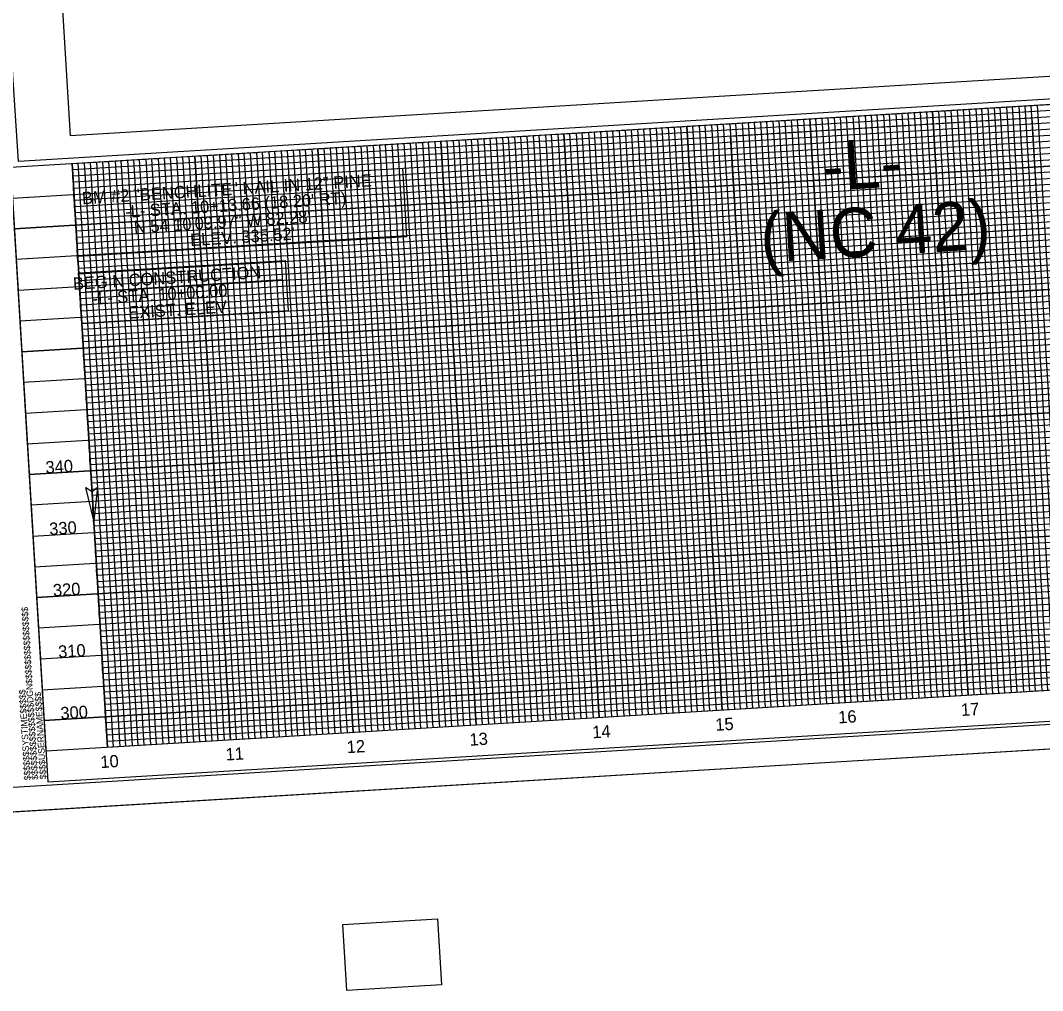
# Model space of a CAD drawing. Extents: x 2110128 to 2112690, y 669500 to 671339.
# Drawn here: x 2110982 to 2111812, y 669502 to 670290 of the extents above; entities that cross this region are included whole.
import ezdxf

# ---------------------------------------------------------------- set-up
doc = ezdxf.new("R2010")
doc.units = 0
for name, color, linetype in [('COGO Default Chain', 7, 'Continuous'), ('Exist Building', 7, 'Continuous'), ('Exist Building Leader', 7, 'Continuous'), ('Exist Guardrail', 7, 'Continuous'), ('Exist Other Culture Area Outline', 7, 'Continuous'), ('Exist Other Culture Fence Line', 7, 'Continuous'), ('Exist Other Culture Sign Leader', 7, 'Continuous'), ('Exist Roads Curbs', 7, 'Continuous'), ('Exist Roads Curbs Text', 7, 'Continuous'), ('Exist Roads EOP Other Text', 7, 'Continuous'), ('Exist Roads Soil', 7, 'Continuous'), ('Exist Structure Minor Footbridge', 7, 'Continuous'), ('Exist Structure Minor Pipes CMP 60 Inch', 7, 'Continuous'), ('Exist Utilities TV Hand Hole CELL', 7, 'Continuous'), ('Exist Utilities TV Test Hole SUE LOS A Text', 7, 'Continuous'), ('Exist Utilities Water Fire Hydrant CELL', 7, 'Continuous'), ('Exist Utilities Water Fire Hydrant Cogo Number', 7, 'Continuous'), ('Exist Utilities Water Test Hole SUE LOS A Text', 7, 'Continuous')]:
    doc.layers.add(name, color=color, linetype=linetype)

msp = doc.modelspace()

# ---------------------------------------------------------------- linework, layer by layer
at = {"layer": 'COGO Default Chain'}
for points in [[(2111558.56, 670196.14), (2111803.11, 670210.96), (2111810.07, 670096.17), (2111565.52, 670081.35)], [(2111025.15, 670153.72), (2111292.17, 670169.9), (2111295.54, 670114.39), (2111028.52, 670098.2)], [(2111029.32, 670085.02), (2111196.98, 670095.18), (2111199.47, 670054.16), (2111031.8, 670044)], [(2111243.72, 669555.89), (2111320.65, 669560.56), (2111323.9, 669506.88), (2111246.97, 669502.22)]]:
    msp.add_lwpolyline(points, close=True, dxfattribs=at)
at = {"layer": 'Exist Building'}
for points in [[(2110974.03, 670170.73), (2112471.28, 670261.48)], [(2111751.39, 669741.97), (2111722.66, 670216.1), (2111772.56, 670219.13), (2111801.3, 669745)], [(2112474.31, 670211.57), (2110977.05, 670120.82), (2110980.08, 670070.92), (2112477.33, 670161.66)], [(2111651.57, 669735.92), (2111622.84, 670210.05), (2111672.75, 670213.08), (2111701.48, 669738.95)], [(2111451.94, 669723.83), (2111423.21, 670197.96), (2111473.11, 670200.98), (2111501.85, 669726.85)], [(2111551.76, 669729.88), (2111523.02, 670204.01), (2111572.93, 670207.03), (2111601.67, 669732.9)], [(2111352.12, 669717.78), (2111323.39, 670191.91), (2111373.3, 670194.93), (2111402.03, 669720.8)], [(2111152.49, 669705.68), (2111123.76, 670179.81), (2111173.66, 670182.83), (2111202.4, 669708.7)], [(2111252.31, 669711.73), (2111223.57, 670185.86), (2111273.48, 670188.88), (2111302.22, 669714.75)], [(2111052.67, 669699.63), (2111023.94, 670173.76), (2111073.85, 670176.78), (2111102.58, 669702.65)], [(2110974.03, 670170.73), (2111002.77, 669696.6)], [(2112480.36, 670111.75), (2110983.1, 670021.01), (2110986.13, 669971.1), (2112483.38, 670061.84)], [(2112486.41, 670011.93), (2110989.15, 669921.19), (2110992.18, 669871.28), (2112489.43, 669962.03)], [(2112492.46, 669912.12), (2110995.2, 669821.37), (2110998.23, 669771.47), (2112495.48, 669862.21)], [(2112498.51, 669812.3), (2111001.25, 669721.56)]]:
    msp.add_lwpolyline(points, dxfattribs=at)
at = {"layer": 'Exist Building Leader'}
for points in [[(2112421.68, 670253.46), (2111024.24, 670168.77)], [(2112422.28, 670243.48), (2111024.85, 670158.79), (2111024.54, 670163.78), (2112421.98, 670248.47)], [(2112423.19, 670228.51), (2111025.75, 670143.81), (2111025.45, 670148.8), (2111025.15, 670153.79), (2112422.58, 670238.49)], [(2112423.79, 670218.52), (2111026.36, 670133.83), (2111026.06, 670138.82), (2112423.49, 670223.52)], [(2111741.41, 669741.37), (2111712.67, 670215.5), (2111717.67, 670215.8), (2111746.4, 669741.67)], [(2111756.38, 669742.28), (2111727.65, 670216.41), (2111732.64, 670216.71), (2111761.37, 669742.58)], [(2111766.36, 669742.88), (2111737.63, 670217.01), (2111742.62, 670217.31), (2111771.36, 669743.18)], [(2111781.34, 669743.79), (2111752.6, 670217.92), (2111757.59, 670218.22), (2111786.33, 669744.09)], [(2111791.32, 669744.39), (2111762.58, 670218.52), (2111767.57, 670218.83), (2111796.31, 669744.7)], [(2111806.29, 669745.3), (2111777.56, 670219.43), (2111782.55, 670219.73), (2111811.28, 669745.6)], [(2111816.27, 669745.91), (2111787.54, 670220.04), (2111792.53, 670220.34), (2111821.26, 669746.21)], [(2111831.25, 669746.81), (2111802.51, 670220.94), (2111807.5, 670221.25), (2111836.24, 669747.12)], [(2112424.7, 670203.55), (2111027.27, 670118.86), (2111026.96, 670123.85), (2111026.66, 670128.84), (2112424.1, 670213.53)], [(2111606.66, 669733.2), (2111577.92, 670207.33), (2111582.91, 670207.64), (2111611.65, 669733.51)], [(2111616.64, 669733.81), (2111587.9, 670207.94), (2111592.89, 670208.24), (2111621.63, 669734.11)], [(2111631.61, 669734.71), (2111602.88, 670208.84), (2111607.87, 670209.15), (2111636.6, 669735.02)], [(2111641.59, 669735.32), (2111612.86, 670209.45), (2111617.85, 670209.75), (2111646.58, 669735.62)], [(2111656.57, 669736.23), (2111627.83, 670210.36), (2111632.82, 670210.66), (2111661.56, 669736.53)], [(2111666.55, 669736.83), (2111637.81, 670210.96), (2111642.8, 670211.26), (2111671.54, 669737.13)], [(2111681.52, 669737.74), (2111652.78, 670211.87), (2111657.78, 670212.17), (2111686.51, 669738.04)], [(2111691.5, 669738.34), (2111662.77, 670212.47), (2111667.76, 670212.78), (2111696.49, 669738.65)], [(2111706.47, 669739.25), (2111677.74, 670213.38), (2111682.73, 670213.68), (2111711.46, 669739.55)], [(2111716.46, 669739.86), (2111687.72, 670213.99), (2111692.71, 670214.29), (2111721.45, 669740.16)], [(2111731.43, 669740.76), (2111702.69, 670214.89), (2111707.68, 670215.2), (2111736.42, 669741.07)], [(2111481.89, 669725.64), (2111453.15, 670199.77), (2111458.14, 670200.07), (2111486.88, 669725.94)], [(2111491.87, 669726.25), (2111463.13, 670200.38), (2111468.12, 670200.68), (2111496.86, 669726.55)], [(2111506.84, 669727.15), (2111478.11, 670201.28), (2111483.1, 670201.59), (2111511.83, 669727.46)], [(2111516.82, 669727.76), (2111488.09, 670201.89), (2111493.08, 670202.19), (2111521.81, 669728.06)], [(2111531.79, 669728.67), (2111503.06, 670202.8), (2111508.05, 670203.1), (2111536.79, 669728.97)], [(2111541.78, 669729.27), (2111513.04, 670203.4), (2111518.03, 670203.7), (2111546.77, 669729.57)], [(2111556.75, 669730.18), (2111528.01, 670204.31), (2111533, 670204.61), (2111561.74, 669730.48)], [(2111566.73, 669730.78), (2111538, 670204.91), (2111542.99, 670205.22), (2111571.72, 669731.09)], [(2111581.7, 669731.69), (2111552.97, 670205.82), (2111557.96, 670206.12), (2111586.69, 669731.99)], [(2111591.68, 669732.3), (2111562.95, 670206.43), (2111567.94, 670206.73), (2111596.68, 669732.6)], [(2112425.31, 670193.57), (2111027.87, 670108.88), (2111027.57, 670113.87), (2112425, 670198.56)], [(2111332.16, 669716.57), (2111303.43, 670190.7), (2111308.42, 670191), (2111337.15, 669716.87)], [(2111342.14, 669717.17), (2111313.41, 670191.3), (2111318.4, 670191.6), (2111347.13, 669717.47)], [(2111357.12, 669718.08), (2111328.38, 670192.21), (2111333.37, 670192.51), (2111362.11, 669718.38)], [(2111367.1, 669718.68), (2111338.36, 670192.81), (2111343.35, 670193.12), (2111372.09, 669718.99)], [(2111382.07, 669719.59), (2111353.33, 670193.72), (2111358.32, 670194.02), (2111387.06, 669719.89)], [(2111392.05, 669720.2), (2111363.32, 670194.33), (2111368.31, 670194.63), (2111397.04, 669720.5)], [(2111407.02, 669721.1), (2111378.29, 670195.23), (2111383.28, 670195.54), (2111412.01, 669721.41)], [(2111417.01, 669721.71), (2111388.27, 670195.84), (2111393.26, 670196.14), (2111422, 669722.01)], [(2111431.98, 669722.62), (2111403.24, 670196.75), (2111408.23, 670197.05), (2111436.97, 669722.92)], [(2111441.96, 669723.22), (2111413.22, 670197.35), (2111418.22, 670197.65), (2111446.95, 669723.52)], [(2111456.93, 669724.13), (2111428.2, 670198.26), (2111433.19, 670198.56), (2111461.92, 669724.43)], [(2111466.91, 669724.73), (2111438.18, 670198.86), (2111443.17, 670199.17), (2111471.9, 669725.04)], [(2112426.21, 670178.6), (2111028.78, 670093.9), (2111028.48, 670098.9), (2111028.17, 670103.89), (2112425.61, 670188.58)], [(2111207.39, 669709), (2111178.65, 670183.13), (2111183.65, 670183.44), (2111212.38, 669709.31)], [(2111217.37, 669709.61), (2111188.64, 670183.74), (2111193.63, 670184.04), (2111222.36, 669709.91)], [(2111232.34, 669710.52), (2111203.61, 670184.65), (2111208.6, 670184.95), (2111237.33, 669710.82)], [(2111242.33, 669711.12), (2111213.59, 670185.25), (2111218.58, 670185.55), (2111247.32, 669711.42)], [(2111257.3, 669712.03), (2111228.56, 670186.16), (2111233.55, 670186.46), (2111262.29, 669712.33)], [(2111267.28, 669712.63), (2111238.54, 670186.76), (2111243.54, 670187.07), (2111272.27, 669712.94)], [(2111282.25, 669713.54), (2111253.52, 670187.67), (2111258.51, 670187.97), (2111287.24, 669713.84)], [(2111292.23, 669714.15), (2111263.5, 670188.28), (2111268.49, 670188.58), (2111297.23, 669714.45)], [(2111307.21, 669715.05), (2111278.47, 670189.18), (2111283.46, 670189.49), (2111312.2, 669715.36)], [(2111317.19, 669715.66), (2111288.45, 670189.79), (2111293.44, 670190.09), (2111322.18, 669715.96)], [(2111057.66, 669699.93), (2111028.93, 670174.06), (2111033.92, 670174.36), (2111062.66, 669700.23)], [(2111067.65, 669700.54), (2111038.91, 670174.67), (2111043.9, 670174.97), (2111072.64, 669700.84)], [(2111082.62, 669701.44), (2111053.88, 670175.57), (2111058.87, 670175.88), (2111087.61, 669701.75)], [(2111092.6, 669702.05), (2111063.87, 670176.18), (2111068.86, 670176.48), (2111097.59, 669702.35)], [(2111107.57, 669702.95), (2111078.84, 670177.08), (2111083.83, 670177.39), (2111112.56, 669703.26)], [(2111117.55, 669703.56), (2111088.82, 670177.69), (2111093.81, 670177.99), (2111122.55, 669703.86)], [(2111132.53, 669704.47), (2111103.79, 670178.6), (2111108.78, 670178.9), (2111137.52, 669704.77)], [(2111142.51, 669705.07), (2111113.77, 670179.2), (2111118.76, 670179.5), (2111147.5, 669705.37)], [(2111157.48, 669705.98), (2111128.75, 670180.11), (2111133.74, 670180.41), (2111162.47, 669706.28)], [(2111167.46, 669706.58), (2111138.73, 670180.71), (2111143.72, 670181.02), (2111172.45, 669706.89)], [(2111182.44, 669707.49), (2111153.7, 670181.62), (2111158.69, 670181.92), (2111187.43, 669707.79)], [(2111192.42, 669708.1), (2111163.68, 670182.23), (2111168.67, 670182.53), (2111197.41, 669708.4)], [(2112426.82, 670168.62), (2111029.38, 670083.92), (2111029.08, 670088.91), (2112426.52, 670173.61)], [(2111030.29, 670068.95), (2111029.99, 670073.94), (2111029.69, 670078.93), (2112427.12, 670163.63)], [(2112428.03, 670148.65), (2111030.59, 670063.96), (2111030.29, 670068.95), (2112427.73, 670153.64)], [(2112428.63, 670138.67), (2111031.2, 670053.98), (2111030.9, 670058.97), (2112428.33, 670143.66)], [(2112429.54, 670123.7), (2111032.11, 670039), (2111031.8, 670044), (2112429.24, 670128.69)], [(2112430.15, 670113.72), (2111032.71, 670029.02), (2111032.41, 670034.01), (2112429.84, 670118.71)], [(2112431.05, 670098.74), (2111033.62, 670014.05), (2111033.32, 670019.04), (2112430.75, 670103.73)], [(2112431.66, 670088.76), (2111034.22, 670004.07), (2111033.92, 670009.06), (2112431.36, 670093.75)], [(2112432.57, 670073.79), (2111035.13, 669989.1), (2111034.83, 669994.09), (2112432.26, 670078.78)], [(2112433.17, 670063.81), (2111035.74, 669979.11), (2111035.43, 669984.11), (2112432.87, 670068.8)], [(2112434.08, 670048.84), (2111036.64, 669964.14), (2111036.34, 669969.13), (2112433.78, 670053.83)], [(2112434.68, 670038.85), (2111037.25, 669954.16), (2111036.94, 669959.15), (2112434.38, 670043.84)], [(2112435.59, 670023.88), (2111038.15, 669939.19), (2111037.85, 669944.18), (2112435.29, 670028.87)], [(2112436.2, 670013.9), (2111038.76, 669929.21), (2111038.46, 669934.2), (2112435.89, 670018.89)], [(2112437.1, 669998.93), (2111039.67, 669914.23), (2111039.36, 669919.22), (2112436.8, 670003.92)], [(2112437.71, 669988.95), (2111040.27, 669904.25), (2111039.97, 669909.24), (2112437.41, 669993.94)], [(2112438.62, 669973.97), (2111041.18, 669889.28), (2111040.88, 669894.27), (2112438.31, 669978.96)], [(2112439.22, 669963.99), (2111041.78, 669879.3), (2111041.48, 669884.29), (2112438.92, 669968.98)], [(2112440.13, 669949.02), (2111042.69, 669864.33), (2111042.39, 669869.32), (2112439.83, 669954.01)], [(2112440.73, 669939.04), (2111043.3, 669854.34), (2111042.99, 669859.33), (2112440.43, 669944.03)], [(2112441.64, 669924.06), (2111044.2, 669839.37), (2111043.9, 669844.36), (2112441.34, 669929.06)], [(2112442.25, 669914.08), (2111044.81, 669829.39), (2111044.51, 669834.38), (2112441.94, 669919.07)], [(2112443.15, 669899.11), (2111045.72, 669814.42), (2111045.41, 669819.41), (2112442.85, 669904.1)], [(2112443.76, 669889.13), (2111046.32, 669804.44), (2111046.02, 669809.43), (2112443.46, 669894.12)], [(2112444.67, 669874.16), (2111047.23, 669789.46), (2111046.93, 669794.45), (2112444.36, 669879.15)], [(2112445.27, 669864.17), (2111047.83, 669779.48), (2111047.53, 669784.47), (2112444.97, 669869.17)], [(2111048.74, 669764.51), (2111048.44, 669769.5), (2112445.87, 669854.19)], [(2111052.37, 669704.62), (2112449.81, 669789.31), (2112449.5, 669794.3), (2111052.07, 669709.61), (2111051.77, 669714.6), (2112449.2, 669799.29), (2112448.9, 669804.28), (2111051.46, 669719.59), (2111051.16, 669724.58), (2111050.86, 669729.57), (2112448.29, 669814.27), (2112447.99, 669819.26), (2111050.56, 669734.56), (2111050.25, 669739.55), (2112447.69, 669824.25), (2112447.39, 669829.24), (2111049.95, 669744.55), (2111049.65, 669749.54), (2111049.35, 669754.53), (2112446.78, 669839.22), (2112446.48, 669844.21), (2111049.04, 669759.52), (2111048.74, 669764.51), (2112446.18, 669849.2)]]:
    msp.add_lwpolyline(points, dxfattribs=at)
at = {"layer": 'Exist Guardrail'}
for p, q in [((2111034.54, 670069.57), (2111194.63, 670079.51)), ((2111031.8, 670044), (2111041.51, 669883.85))]:
    msp.add_line(p, q, dxfattribs=at)
at = {"layer": 'Exist Other Culture Area Outline'}
for p, q in [((2110975.54, 670145.78), (2112472.8, 670236.52)), ((2112475.82, 670186.61), (2110978.57, 670095.87)), ((2110981.59, 670045.96), (2112478.84, 670136.7)), ((2112481.87, 670086.8), (2110984.62, 669996.05)), ((2110987.64, 669946.15), (2112484.89, 670036.89)), ((2110984.62, 669996.05), (2110987.64, 669946.15)), ((2112487.92, 669986.98), (2110990.67, 669896.24)), ((2110993.69, 669846.33), (2112490.94, 669937.07)), ((2110990.67, 669896.24), (2110993.69, 669846.33)), ((2112493.97, 669887.16), (2110996.72, 669796.42)), ((2110999.74, 669746.51), (2112496.99, 669837.25)), ((2110996.72, 669796.42), (2110999.74, 669746.51))]:
    msp.add_line(p, q, dxfattribs=at)
for points in [[(2111776.35, 669743.49), (2111747.61, 670217.62), (2111797.52, 670220.64), (2111826.25, 669746.51)], [(2111576.71, 669731.39), (2111547.98, 670205.52), (2111597.89, 670208.54), (2111626.62, 669734.41)], [(2111676.53, 669737.44), (2111647.79, 670211.57), (2111697.7, 670214.59), (2111726.44, 669740.46)], [(2111476.9, 669725.34), (2111448.16, 670199.47), (2111498.07, 670202.49), (2111526.8, 669728.36)], [(2111377.08, 669719.29), (2111348.34, 670193.42), (2111398.25, 670196.44), (2111426.99, 669722.31)], [(2111177.44, 669707.19), (2111148.71, 670181.32), (2111198.62, 670184.34), (2111227.35, 669710.21)], [(2111277.26, 669713.24), (2111248.53, 670187.37), (2111298.43, 670190.39), (2111327.17, 669716.26)], [(2111077.63, 669701.14), (2111048.89, 670175.27), (2111098.8, 670178.29), (2111127.54, 669704.16)]]:
    msp.add_lwpolyline(points, dxfattribs=at)
at = {"layer": 'Exist Other Culture Sign Leader'}
msp.add_lwpolyline([(2111023.94, 670173.76), (2112421.37, 670258.45), (2112450.11, 669784.32), (2111052.67, 669699.63)], close=True, dxfattribs=at)
at = {"layer": 'Exist Roads Curbs'}
msp.add_line((2110839.44, 669639.12), (2112519.86, 669740.96), dxfattribs=at)
at = {"layer": 'Exist Roads Curbs Text'}
for p, q in [((2112500.02, 669787.35), (2111002.77, 669696.6)), ((2111004.28, 669671.65), (2111004.28, 669671.65)), ((2111004.28, 669671.65), (2111004.28, 669671.65)), ((2111004.28, 669671.65), (2111004.28, 669671.65)), ((2111004.28, 669671.65), (2111004.28, 669671.65)), ((2111004.28, 669671.65), (2111004.28, 669671.65))]:
    msp.add_line(p, q, dxfattribs=at)
msp.add_lwpolyline([(2112438.01, 670810.47), (2110940.76, 670719.73), (2111004.28, 669671.65), (2112501.53, 669762.39)], close=True, dxfattribs=at)
at = {"layer": 'Exist Roads EOP Other Text'}
msp.add_lwpolyline([(2110851.21, 669659.87), (2112514.16, 669760.65), (2112450.34, 670813.72), (2110787.39, 670712.94)], close=True, dxfattribs=at)
at = {"layer": 'Exist Roads Soil'}
msp.add_line((2111004.28, 669671.65), (2111004.28, 669671.65), dxfattribs=at)
at = {"layer": 'Exist Utilities TV Hand Hole CELL'}
for p, q in [((2110974.03, 670170.73), (2112471.28, 670261.48)), ((2111722.66, 670216.1), (2111751.39, 669741.97)), ((2111772.56, 670219.13), (2111801.3, 669745)), ((2110977.05, 670120.82), (2112474.31, 670211.57)), ((2111622.84, 670210.05), (2111651.57, 669735.92)), ((2111672.75, 670213.08), (2111701.48, 669738.95)), ((2111473.11, 670200.98), (2111501.85, 669726.85)), ((2111523.02, 670204.01), (2111551.76, 669729.88)), ((2111572.93, 670207.03), (2111601.67, 669732.9)), ((2111323.39, 670191.91), (2111352.12, 669717.78)), ((2111373.3, 670194.93), (2111402.03, 669720.8)), ((2111423.21, 670197.96), (2111451.94, 669723.83)), ((2111173.66, 670182.83), (2111202.4, 669708.7)), ((2111223.57, 670185.86), (2111252.31, 669711.73)), ((2111273.48, 670188.88), (2111302.22, 669714.75)), ((2111073.85, 670176.78), (2111102.58, 669702.65)), ((2111123.76, 670179.81), (2111152.49, 669705.68)), ((2111023.94, 670173.76), (2111052.67, 669699.63)), ((2110980.08, 670070.92), (2112477.33, 670161.66)), ((2110983.1, 670021.01), (2112480.36, 670111.75)), ((2110986.13, 669971.1), (2112483.38, 670061.84)), ((2110989.15, 669921.19), (2112486.41, 670011.93)), ((2110992.18, 669871.28), (2112489.43, 669962.03)), ((2110995.2, 669821.37), (2112492.46, 669912.12)), ((2110998.23, 669771.47), (2112495.48, 669862.21)), ((2111001.25, 669721.56), (2112498.51, 669812.3))]:
    msp.add_line(p, q, dxfattribs=at)
at = {"layer": 'Exist Utilities TV Test Hole SUE LOS A Text'}
msp.add_lwpolyline([(2111022.58, 670196.24), (2110993.69, 670672.84), (2112191.44, 670745.43), (2112200.05, 670603.34), (2112399.74, 670615.44), (2112420.01, 670280.93)], close=True, dxfattribs=at)
at = {"layer": 'Exist Utilities Water Fire Hydrant CELL'}
msp.add_lwpolyline([(2110944.98, 670715.17), (2112189.1, 670790.57), (2112200.05, 670603.34), (2112399.74, 670615.44), (2112418.35, 670308.36), (2112421.12, 670262.68), (2110980.52, 670175.37)], close=True, dxfattribs=at)
at = {"layer": 'Exist Utilities Water Fire Hydrant Cogo Number'}
msp.add_lwpolyline([(2111044.65, 669911.07), (2111041.51, 669883.85), (2111035.21, 669910.7), (2111040.19, 669907.52)], close=True, dxfattribs=at)
at = {"layer": 'Exist Utilities Water Test Hole SUE LOS A Text'}
msp.add_lwpolyline([(2110839.44, 669639.12), (2112519.86, 669740.96), (2112453.62, 670833.96), (2110773.2, 670732.11)], close=True, dxfattribs=at)

# ---------------------------------------------------------------- texts
at = {"layer": 'Exist Other Culture Fence Line'}
for s, height, rotation, p in [('-L-', 40, 3.46824, (2111633.68, 670151.42)), ('BM #2 "BENCHLITE" NAIL IN 12" PINE', 10, 3.55203, (2111032.31, 670140.66)), ("-L- STA. 10+13.66 (18.20' RT)", 10, 3.55203, (2111067.38, 670129.7)), ('(NC 42)', 40, 3.46824, (2111583.84, 670093.3)), ('N 54 10\'09.97" W 82.28\'', 10, 3.55203, (2111074.49, 670117.01)), ('O', 3, 3.46824, (2111110.19, 670126.57)), ("ELEV. 335.52'", 10, 3.55203, (2111120.15, 670106.71)), ('  BEGIN CONSTRUCTION', 10, 3.55203, (2111017.63, 670070.79)), ('    -L- STA. 10+00.00', 10, 3.55203, (2111026.07, 670058.18)), ('EXIST. ELEV.', 10, 3.55203, (2111069.92, 670047.77))]:
    msp.add_text(s, height=height, rotation=rotation, dxfattribs=at).set_placement(p)
at = {"layer": 'Exist Roads Soil'}
for s, p in [('$$$$$$$$$$$$$$$$DGN$$$$$$$$$$$$$$$$', (2110996.5, 669673.54)), ('$$$$$$SYSTIME$$$$$', (2110990.46, 669673.18)), ('$$$$USERNAME$$$$', (2111003.06, 669673.95))]:
    msp.add_text(s, height=5.25, rotation=93.46824, dxfattribs=at).set_placement(p)
at = {"layer": 'Exist Structure Minor Footbridge'}
for s, p in [('17', (2111745.94, 669725.16)), ('16', (2111646.26, 669719.12)), ('15', (2111546.51, 669713.07)), ('13', (2111346.94, 669700.98)), ('14', (2111446.6, 669707.02)), ('12', (2111247.29, 669694.94)), ('10', (2111047.26, 669682.82)), ('11', (2111148.92, 669688.98))]:
    msp.add_text(s, height=10, rotation=3.46824, dxfattribs=at).set_placement(p)
at = {"layer": 'Exist Structure Minor Pipes CMP 60 Inch'}
for s, p in [('340', (2111002.71, 669922.01)), ('330', (2111005.74, 669872.1)), ('320', (2111008.76, 669822.2)), ('310', (2111012.98, 669772.36)), ('300', (2111014.81, 669722.38))]:
    msp.add_text(s, height=10, rotation=3.46824, dxfattribs=at).set_placement(p)

doc.saveas('drawing.dxf')
